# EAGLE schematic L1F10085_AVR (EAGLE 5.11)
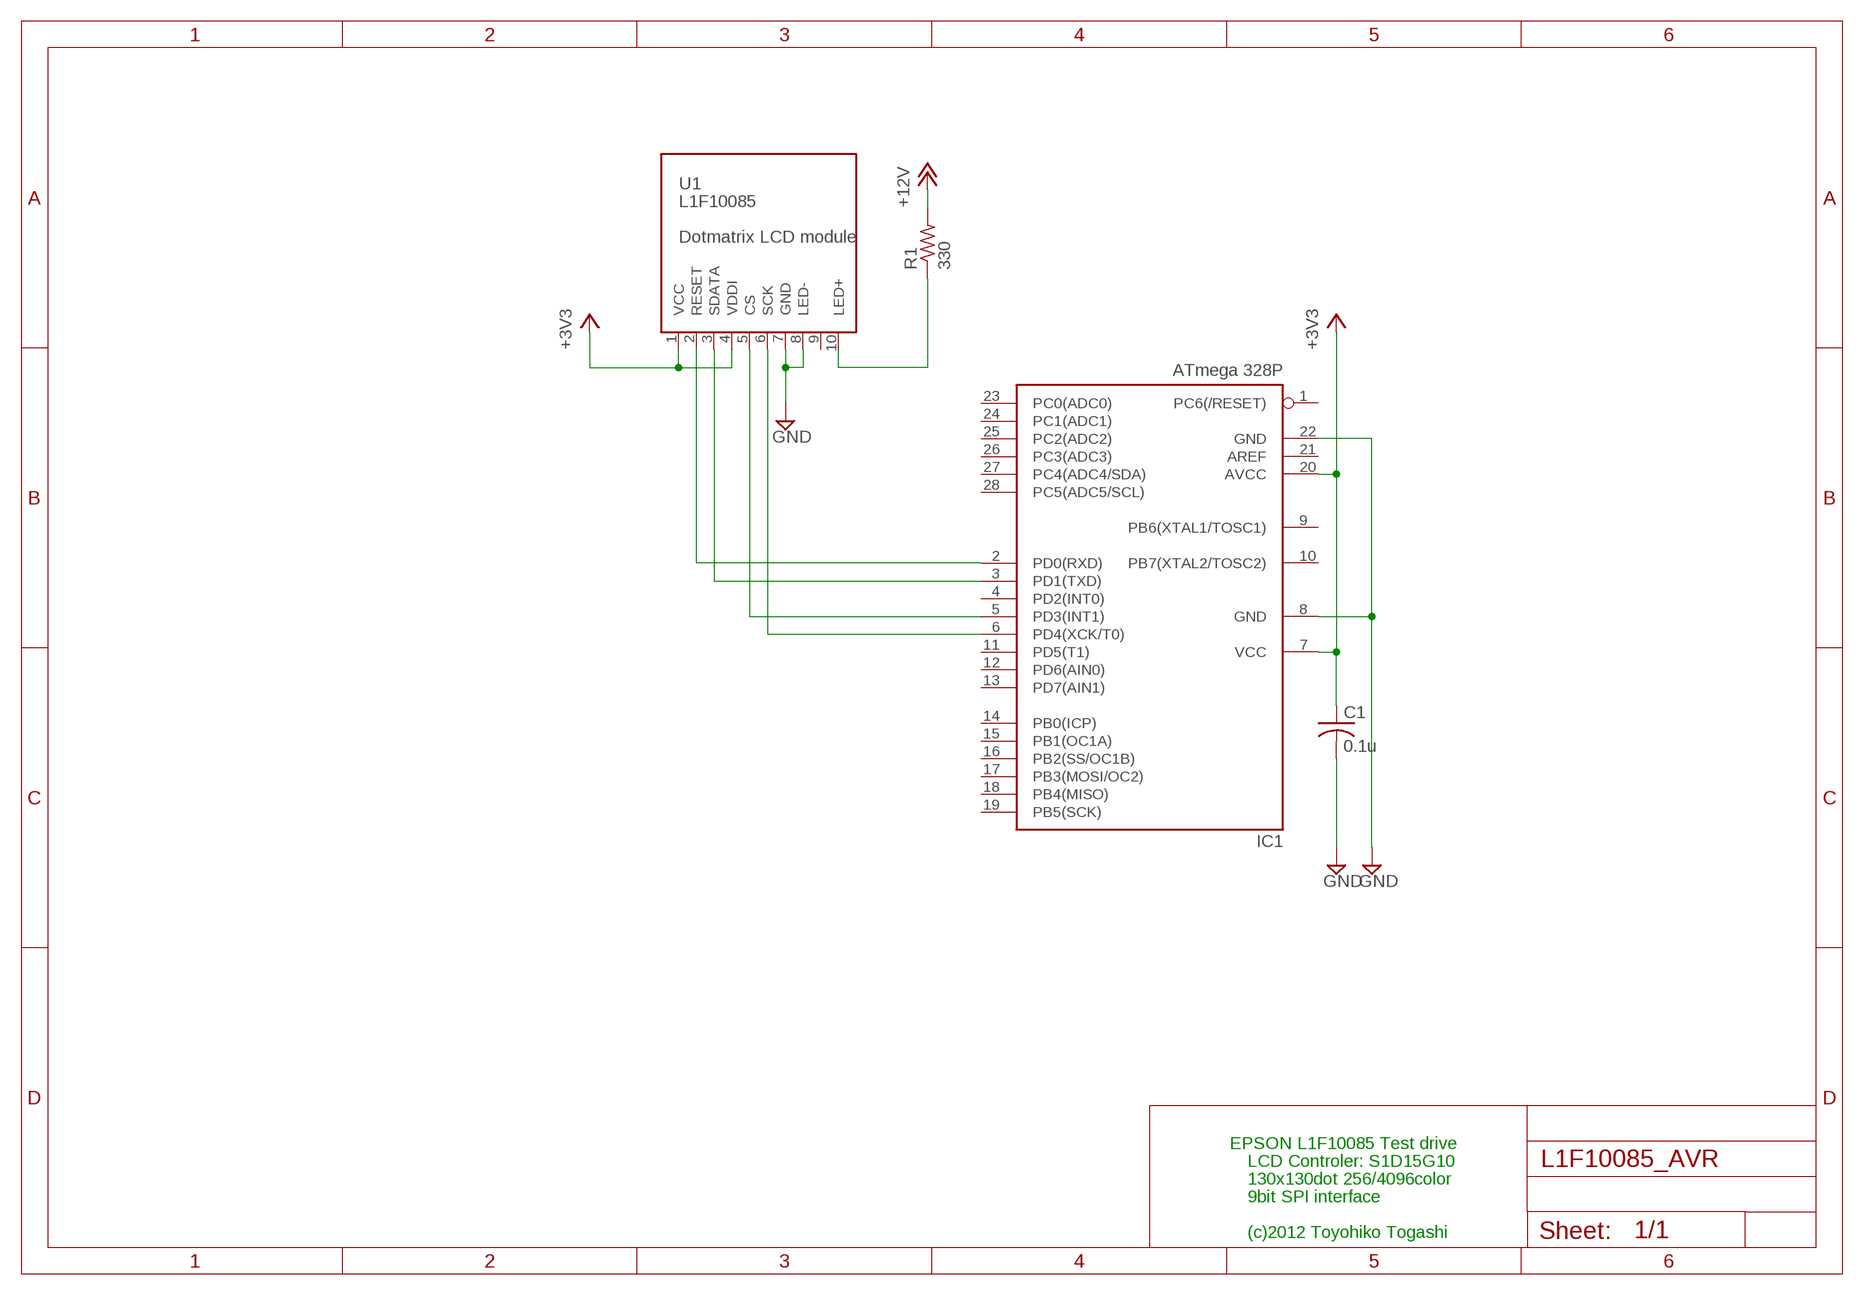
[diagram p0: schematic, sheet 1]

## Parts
C1  0.1u  C-US025-024X044  [C025-024X044]
IC1  ATmega 328P  MEGA8-P  [DIL28-3]
R1  330  R-US_0204/5  [0204/5]
U1  L1F10085  [L1F10085]

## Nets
+3V3: C1.1 IC1.7(VCC) IC1.20(AVCC) U1.1(VCC) U1.4(VDDI)
+12V: R1.2
GND: C1.2 IC1.8(GND) IC1.22(GND) U1.7(GND) U1.8(LED-)
N$1: R1.1 U1.10(LED+)
N$3: IC1.2(PD0(RXD)) U1.2(RESET)
N$4: IC1.3(PD1(TXD)) U1.3(SDATA)
N$5: IC1.5(PD3(INT1)) U1.5(CS)
N$6: IC1.6(PD4(XCK/T0)) U1.6(SCK)
Unconnected: IC1.1(PC6(/RESET)) IC1.4(PD2(INT0)) IC1.9(PB6(XTAL1/TOSC1)) IC1.10(PB7(XTAL2/TOSC2)) IC1.11(PD5(T1)) IC1.12(PD6(AIN0)) IC1.13(PD7(AIN1)) IC1.14(PB0(ICP)) IC1.15(PB1(OC1A)) IC1.16(PB2(SS/OC1B)) IC1.17(PB3(MOSI/OC2)) IC1.18(PB4(MISO)) IC1.19(PB5(SCK)) IC1.21(AREF) IC1.23(PC0(ADC0)) IC1.24(PC1(ADC1)) IC1.25(PC2(ADC2)) IC1.26(PC3(ADC3)) IC1.27(PC4(ADC4/SDA)) IC1.28(PC5(ADC5/SCL)) U1.9

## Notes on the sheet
- EPSON L1F10085 Test drive
- LCD Controler: S1D15G10
- 130x130dot 256/4096color
- 9bit SPI interface
- (c)2012 Toyohiko Togashi

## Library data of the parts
C1 = rcl:C-US: CAPACITOR, American symbol
IC1 = atmel:MEGA8-P: MICROCONTROLLER 8 Kbytes FLASH, 1 kbytes SRAM, 512 bytes EEPROM, USART, 4-channel 10 bit ADC, 2-channel 8 bit ADC Pin compatible with Atmega48, ATMega88, ATMega168 Source: avr.lbr
R1 = rcl:R-US_: RESISTOR, American symbol
U1 = TOG:L1F10085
